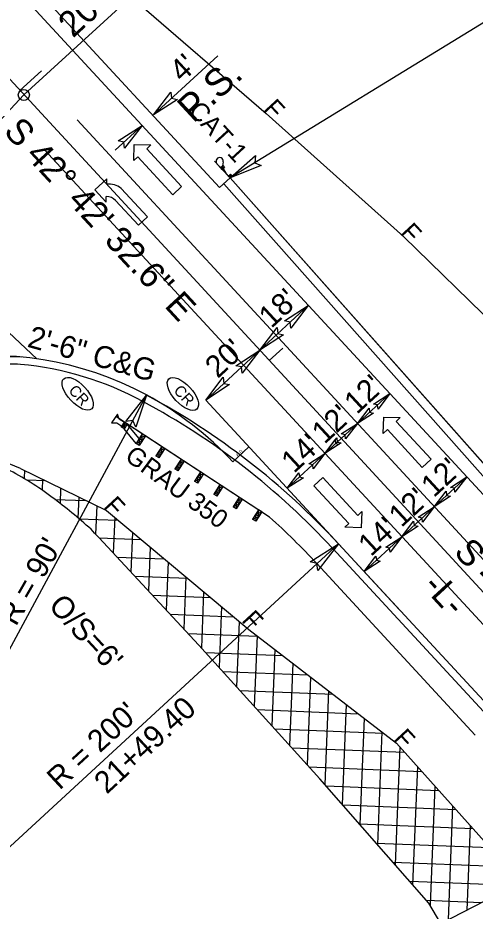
# Model space of a CAD drawing. Extents: x 1702862 to 1704514, y 793768 to 796215.
# Drawn here: x 1703331.8 to 1703456.2, y 795003.7 to 795246.9 of the extents above; entities that cross this region are included whole.
import ezdxf

# ---------------------------------------------------------------- set-up
doc = ezdxf.new("R2010")
doc.units = 0
for name, color, linetype in [('Default', 7, 'Continuous'), ('Prop Conc 2ft 6in Curb and Gutter', 7, 'Continuous'), ('Prop Conc Shoulder Berm Gutter', 7, 'Continuous'), ('Prop Dimension', 7, 'Continuous'), ('Prop Dimension Text', 7, 'Continuous'), ('Prop DSN Text', 7, 'Continuous'), ('Prop EOT', 7, 'Continuous'), ('Prop Guardrail', 7, 'Continuous'), ('Prop Guardrail Anchor Unit CELL', 7, 'Continuous'), ('Prop Horizontal Alignment', 7, 'Continuous'), ('Prop Horizontal Alignment Direction Label', 7, 'Continuous'), ('Prop Horizontal Alignment Station Label', 7, 'Continuous'), ('Prop Horizontal Alignment Tick Label', 7, 'Continuous'), ('Prop Horizontal Alignment Tick Large', 7, 'Continuous'), ('Prop Horizontal Alignment Tick Small', 7, 'Continuous'), ('Prop Lane Arrow CELL', 7, 'Continuous'), ('Prop Lane Lines', 7, 'Continuous'), ('Prop Leader Line Medium', 7, 'Continuous'), ('Prop Paved Shoulder', 7, 'Continuous'), ('Prop Rem of Exist Asph Pvmt', 7, 'Continuous'), ('Prop SS Fill Line', 7, 'Continuous'), ('Prop SS Misc', 7, 'Continuous'), ('Prop SS Transition Line', 7, 'Continuous'), ('Prop Structure Anchor Unit CELL', 7, 'Continuous'), ('Prop Superelevation  Arrow CELL', 7, 'Continuous'), ('Prop Terminator CELL', 7, 'Continuous'), ('Prop WCR CELL', 7, 'Continuous')]:
    doc.layers.add(name, color=color, linetype=linetype)

msp = doc.modelspace()

# ---------------------------------------------------------------- linework, layer by layer
at = {"layer": 'Default'}
msp.add_line((1703382.89, 795142.89), (1703435.5, 795085.89), dxfattribs=at)
at = {"layer": 'Prop Conc 2ft 6in Curb and Gutter'}
msp.add_line((1703417.51, 795102.43), (1703474.32, 795040.89), dxfattribs=at)
for centre, radius, start, end in [((1703330.77, 795134.69), 18, 84.5561, 126.0894), ((1703324.13, 795065.01), 88, 61.7203, 84.5561), ((1703272.02, 794968.13), 198, 42.7091, 61.7203)]:
    msp.add_arc(centre, radius, start, end, dxfattribs=at)
at = {"layer": 'Prop Conc Shoulder Berm Gutter'}
msp.add_line((1703389.53, 795203.37), (1703514.68, 795062.03), dxfattribs=at)
at = {"layer": 'Prop Dimension'}
for p, q in [((1703368.67, 795220.51), (1703386.16, 795236.65)), ((1703358.27, 795210.9), (1703365.58, 795217.66)), ((1703397.58, 795156.45), (1703410.81, 795168.66)), ((1703382.89, 795142.89), (1703397.58, 795156.45)), ((1703272.02, 794968.13), (1703366.77, 795144.26)), ((1703324.13, 795065.01), (1703366.77, 795144.26)), ((1703424.16, 795136.51), (1703432.98, 795144.65)), ((1703415.34, 795128.37), (1703424.16, 795136.51)), ((1703390.26, 795126.05), (1703394.67, 795130.12)), ((1703405.06, 795118.87), (1703415.34, 795128.37)), ((1703445.09, 795113.83), (1703453.91, 795121.97)), ((1703436.27, 795105.69), (1703445.09, 795113.83)), ((1703425.99, 795096.2), (1703436.27, 795105.69)), ((1703272.02, 794968.13), (1703418.98, 795103.79))]:
    msp.add_line(p, q, dxfattribs=at)
for start, end in [(136.7565, 136.7565), (42.7091, 61.7203)]:
    msp.add_arc((1703324.13, 795065.01), 90, start, end, dxfattribs=at)
at = {"layer": 'Prop EOT'}
for p, q in [((1703259.9, 795332.15), (1703737.14, 794815.13)), ((1703418.98, 795103.79), (1703631.9, 794873.13))]:
    msp.add_line(p, q, dxfattribs=at)
for centre, radius, start, end in [((1703324.13, 795065.01), 90, 61.7203, 136.7565), ((1703330.77, 795134.69), 20, 84.5561, 126.0894), ((1703272.02, 794968.13), 200, 42.7091, 61.7203)]:
    msp.add_arc(centre, radius, start, end, dxfattribs=at)
at = {"layer": 'Prop Guardrail'}
for p, q in [((1703389.53, 795203.37), (1703385.29, 795207.96)), ((1703518.92, 795057.44), (1703389.53, 795203.37)), ((1703400.26, 795111.03), (1703358.41, 795138.39)), ((1703413.1, 795098.36), (1703456.19, 795051.68))]:
    msp.add_line(p, q, dxfattribs=at)
msp.add_arc((1703272.02, 794968.13), 192, 42.7091, 48.0924, dxfattribs=at)
at = {"layer": 'Prop Guardrail Anchor Unit CELL'}
for p, q in [((1703387.12, 795205.97), (1703385.96, 795207.23)), ((1703386.94, 795206.17), (1703387.54, 795206.71)), ((1703387.42, 795205.65), (1703387.54, 795206.71)), ((1703387.66, 795207.73), (1703387.46, 795206.65)), ((1703387.54, 795206.71), (1703388.01, 795206.2)), ((1703386.94, 795206.17), (1703388.01, 795206.2)), ((1703387.42, 795205.65), (1703386.94, 795206.17)), ((1703387.03, 795206.07), (1703387.12, 795205.97)), ((1703389.53, 795203.37), (1703387.12, 795205.97)), ((1703388.01, 795206.2), (1703387.42, 795205.65)), ((1703387.48, 795206.18), (1703388.47, 795204.51)), ((1703389.05, 795203.88), (1703389.64, 795204.43)), ((1703389.53, 795203.37), (1703389.64, 795204.43)), ((1703389.64, 795204.43), (1703390.12, 795203.92)), ((1703389.05, 795203.88), (1703390.12, 795203.92)), ((1703389.53, 795203.37), (1703389.05, 795203.88)), ((1703390.12, 795203.92), (1703389.53, 795203.37)), ((1703358.88, 795139.09), (1703357.23, 795136.66)), ((1703359.37, 795137.72), (1703358.88, 795139.09)), ((1703357.23, 795136.66), (1703358.69, 795136.71)), ((1703358.69, 795136.71), (1703360.38, 795135.56)), ((1703361.07, 795136.57), (1703359.37, 795137.72)), ((1703360.71, 795136.89), (1703359.89, 795135.63)), ((1703359.89, 795135.63), (1703361.55, 795136.34)), ((1703360.38, 795135.56), (1703360.72, 795136.06)), ((1703360.71, 795136.89), (1703360.73, 795135.09)), ((1703360.72, 795136.06), (1703361.07, 795136.57)), ((1703361.55, 795136.34), (1703360.73, 795135.09)), ((1703400.26, 795111.03), (1703361.13, 795136.61)), ((1703364.81, 795132.38), (1703361.55, 795136.34)), ((1703360.73, 795135.09), (1703359.89, 795135.63)), ((1703360.73, 795135.09), (1703360.31, 795135.36)), ((1703363.98, 795131.09), (1703360.73, 795135.09)), ((1703365.65, 795133.66), (1703363.98, 795131.09)), ((1703365.65, 795131.83), (1703365.65, 795133.66)), ((1703363.98, 795131.09), (1703365.65, 795131.83)), ((1703366.49, 795133.11), (1703364.81, 795130.55)), ((1703366.49, 795133.11), (1703364.81, 795132.38)), ((1703365.65, 795131.83), (1703364.81, 795132.38)), ((1703364.81, 795132.38), (1703364.81, 795130.55)), ((1703364.81, 795130.55), (1703363.98, 795131.09)), ((1703370.93, 795130.21), (1703369.29, 795127.7)), ((1703371.76, 795129.66), (1703370.11, 795128.95)), ((1703370.94, 795128.41), (1703370.11, 795128.95)), ((1703370.11, 795128.95), (1703370.12, 795127.15)), ((1703371.76, 795129.66), (1703370.12, 795127.15)), ((1703370.94, 795128.41), (1703370.93, 795130.21)), ((1703369.29, 795127.7), (1703370.94, 795128.41)), ((1703370.12, 795127.15), (1703369.29, 795127.7)), ((1703376.2, 795126.76), (1703374.48, 795124.13)), ((1703376.18, 795124.9), (1703376.2, 795126.76)), ((1703374.48, 795124.13), (1703376.18, 795124.9)), ((1703375.32, 795123.59), (1703374.48, 795124.13)), ((1703377.04, 795126.21), (1703375.32, 795123.59)), ((1703375.34, 795125.45), (1703375.32, 795123.59)), ((1703377.04, 795126.21), (1703375.34, 795125.45)), ((1703376.18, 795124.9), (1703375.34, 795125.45)), ((1703381.47, 795123.31), (1703379.81, 795120.77)), ((1703379.81, 795120.77), (1703381.48, 795121.49)), ((1703382.31, 795122.76), (1703380.64, 795122.04)), ((1703381.48, 795121.49), (1703380.64, 795122.04)), ((1703380.64, 795122.04), (1703380.65, 795120.22)), ((1703382.31, 795122.76), (1703380.65, 795120.22)), ((1703382.31, 795122.76), (1703381.47, 795123.31)), ((1703381.48, 795121.49), (1703381.47, 795123.31)), ((1703380.65, 795120.22), (1703379.81, 795120.77)), ((1703386.75, 795119.86), (1703385.08, 795117.31)), ((1703387.58, 795119.31), (1703385.91, 795118.59)), ((1703387.58, 795119.31), (1703385.92, 795116.76)), ((1703386.75, 795118.04), (1703386.75, 795119.86)), ((1703385.08, 795117.31), (1703386.75, 795118.04)), ((1703385.92, 795116.76), (1703385.08, 795117.31)), ((1703386.75, 795118.04), (1703385.91, 795118.59)), ((1703385.91, 795118.59), (1703385.92, 795116.76)), ((1703392.02, 795116.41), (1703390.35, 795113.86)), ((1703390.35, 795113.86), (1703392.02, 795114.59)), ((1703392.86, 795115.87), (1703391.19, 795113.31)), ((1703392.86, 795115.87), (1703391.19, 795115.14)), ((1703392.02, 795114.59), (1703391.19, 795115.14)), ((1703391.19, 795115.14), (1703391.19, 795113.31)), ((1703392.02, 795114.59), (1703392.02, 795116.41)), ((1703391.19, 795113.31), (1703390.35, 795113.86)), ((1703397.29, 795112.96), (1703395.65, 795110.45)), ((1703397.29, 795112.96), (1703396.47, 795111.71)), ((1703396.47, 795111.71), (1703398.13, 795112.42)), ((1703398.13, 795112.42), (1703396.49, 795109.91)), ((1703398.13, 795112.42), (1703397.29, 795112.96)), ((1703397.31, 795111.16), (1703397.29, 795112.96)), ((1703395.65, 795110.45), (1703397.31, 795111.16)), ((1703396.49, 795109.91), (1703395.65, 795110.45)), ((1703397.31, 795111.16), (1703396.47, 795111.71)), ((1703396.47, 795111.71), (1703396.49, 795109.91))]:
    msp.add_line(p, q, dxfattribs=at)
msp.add_ellipse((1703386.69, 795207.91), major_axis=(-0.73, -0.674), ratio=0.995379, start_param=2.210226, end_param=6.283185, dxfattribs=at)
at = {"layer": 'Prop Horizontal Alignment'}
for p, q in [((1703246.67, 795319.94), (1703723.92, 794802.92)), ((1703333.42, 795225.96), (1703157.53, 795038.5))]:
    msp.add_line(p, q, dxfattribs=at)
at = {"layer": 'Prop Horizontal Alignment Station Label'}
msp.add_line((1703333.42, 795225.96), (1703408.81, 795294.97), dxfattribs=at)
msp.add_circle((1703333.42, 795225.96), 1.5, dxfattribs=at)
at = {"layer": 'Prop Horizontal Alignment Tick Large'}
msp.add_line((1703332.34, 795227.14), (1703338.22, 795232.56), dxfattribs=at)
at = {"layer": 'Prop Horizontal Alignment Tick Small'}
msp.add_line((1703400.17, 795153.65), (1703403.84, 795157.05), dxfattribs=at)
at = {"layer": 'Prop Lane Arrow CELL'}
for p, q in [((1703363.33, 795208.07), (1703363.47, 795212.49)), ((1703363.47, 795212.49), (1703367.96, 795212.34)), ((1703367.96, 795212.34), (1703366.86, 795211.32)), ((1703364.43, 795209.09), (1703363.33, 795208.07)), ((1703373.93, 795198.8), (1703364.43, 795209.09)), ((1703366.86, 795211.32), (1703376.35, 795201.04)), ((1703356.04, 795203.09), (1703352.77, 795200.14)), ((1703355.98, 795201.61), (1703356.04, 795203.09)), ((1703352.77, 795200.14), (1703355.79, 795196.8)), ((1703367.02, 795192.75), (1703359.86, 795200.5)), ((1703376.35, 795201.04), (1703373.93, 795198.8)), ((1703355.79, 795196.8), (1703355.85, 795198.29)), ((1703358.39, 795197.23), (1703364.59, 795190.51)), ((1703364.59, 795190.51), (1703367.02, 795192.75)), ((1703431.21, 795133.82), (1703431.35, 795138.24)), ((1703431.35, 795138.24), (1703435.84, 795138.1)), ((1703435.84, 795138.1), (1703434.74, 795137.08)), ((1703434.74, 795137.08), (1703444.24, 795126.79)), ((1703432.31, 795134.84), (1703431.21, 795133.82)), ((1703441.81, 795124.55), (1703432.31, 795134.84)), ((1703444.24, 795126.79), (1703441.81, 795124.55)), ((1703412.35, 795119.55), (1703414.77, 795121.78)), ((1703414.77, 795121.78), (1703424.27, 795111.5)), ((1703421.85, 795109.26), (1703412.35, 795119.55)), ((1703424.27, 795111.5), (1703425.37, 795112.51)), ((1703425.37, 795112.51), (1703425.23, 795108.1)), ((1703420.74, 795108.24), (1703421.85, 795109.26)), ((1703425.23, 795108.1), (1703420.74, 795108.24))]:
    msp.add_line(p, q, dxfattribs=at)
for centre, radius, start, end in [((1703356.6, 795196.41), 5.25, 51.3851, 96.6968), ((1703355.99, 795195.03), 3.27, 42.7091, 92.3672)]:
    msp.add_arc(centre, radius, start, end, dxfattribs=at)
at = {"layer": 'Prop Lane Lines'}
for p, q in [((1703347.89, 795219.14), (1703550.56, 794999.58)), ((1703339.07, 795211), (1703542.22, 794990.92))]:
    msp.add_line(p, q, dxfattribs=at)
at = {"layer": 'Prop Leader Line Medium'}
msp.add_line((1703493.18, 795266.98), (1703389.53, 795203.37), dxfattribs=at)
at = {"layer": 'Prop Paved Shoulder'}
for p, q in [((1703262.84, 795334.86), (1703386.66, 795200.72)), ((1703386.66, 795200.72), (1703389.53, 795203.37)), ((1703387.81, 795201.79), (1703512.55, 795060.91))]:
    msp.add_line(p, q, dxfattribs=at)
at = {"layer": 'Prop Rem of Exist Asph Pvmt'}
for p, q in [((1703333.62, 795123.68), (1703333.54, 795121.71)), ((1703334.48, 795121.15), (1703339.17, 795120.96)), ((1703338.53, 795121.28), (1703338.41, 795118.51)), ((1703343.43, 795118.88), (1703343.27, 795114.67)), ((1703341.81, 795115.85), (1703350.31, 795115.51)), ((1703348.34, 795116.47), (1703348.11, 795110.71)), ((1703353.25, 795114.07), (1703352.94, 795106.37)), ((1703348.26, 795110.59), (1703359.03, 795110.16)), ((1703358.13, 795110.91), (1703357.74, 795101.25)), ((1703352.67, 795106.65), (1703351.72, 795107.76)), ((1703352.67, 795106.65), (1703353.81, 795105.47)), ((1703353.91, 795105.36), (1703365.32, 795104.9)), ((1703362.97, 795106.87), (1703362.54, 795096.09)), ((1703367.81, 795102.82), (1703367.34, 795090.94)), ((1703358.75, 795100.16), (1703371.62, 795099.65)), ((1703372.65, 795098.78), (1703372.13, 795085.79)), ((1703363.59, 795094.96), (1703377.91, 795094.39)), ((1703377.5, 795094.74), (1703376.93, 795080.64)), ((1703382.34, 795090.69), (1703381.73, 795075.46)), ((1703368.43, 795089.77), (1703384.21, 795089.13)), ((1703387.18, 795086.65), (1703386.52, 795070.15)), ((1703373.27, 795084.57), (1703390.5, 795083.88)), ((1703392.02, 795082.61), (1703391.31, 795064.84)), ((1703378.11, 795079.37), (1703396.99, 795078.62)), ((1703396.87, 795078.71), (1703396.1, 795059.53)), ((1703382.89, 795074.18), (1703403.84, 795073.34)), ((1703401.72, 795074.97), (1703400.89, 795054.22)), ((1703406.58, 795071.23), (1703405.69, 795048.91)), ((1703387.57, 795068.98), (1703410.69, 795068.06)), ((1703411.43, 795067.48), (1703410.48, 795043.6)), ((1703392.26, 795063.79), (1703417.54, 795062.78)), ((1703416.29, 795063.74), (1703415.27, 795038.25)), ((1703396.94, 795058.6), (1703424.39, 795057.5)), ((1703421.14, 795060), (1703420.05, 795032.8)), ((1703426, 795056.26), (1703424.84, 795027.34)), ((1703401.63, 795053.41), (1703431.24, 795052.23)), ((1703430.85, 795052.52), (1703429.63, 795021.89)), ((1703406.31, 795048.22), (1703437.01, 795046.99)), ((1703435.69, 795048.47), (1703434.41, 795016.44)), ((1703410.99, 795043.03), (1703441.64, 795041.8)), ((1703440.48, 795043.1), (1703439.2, 795010.99)), ((1703415.63, 795037.84), (1703446.27, 795036.61)), ((1703445.27, 795037.73), (1703443.98, 795005.35)), ((1703420.18, 795032.65), (1703450.9, 795031.42)), ((1703450.06, 795032.37), (1703448.82, 795001.4)), ((1703424.73, 795027.47), (1703455.53, 795026.23)), ((1703454.85, 795027), (1703453.93, 795004.05)), ((1703429.29, 795022.28), (1703460.16, 795021.04)), ((1703433.84, 795017.09), (1703464.79, 795015.85)), ((1703446.88, 795000.39), (1703470.79, 795012.78)), ((1703446.88, 795000.39), (1703470.79, 795012.78)), ((1703438.39, 795011.91), (1703466.9, 795010.77)), ((1703442.94, 795006.72), (1703457.94, 795006.12))]:
    msp.add_line(p, q, dxfattribs=at)
msp.add_lwpolyline([(1703446.88, 795000.39), (1703443.63, 795005.93), (1703413.93, 795039.78), (1703381.07, 795076.19), (1703353.81, 795105.47)], dxfattribs=at)
msp.add_spline([(1703351.72, 795107.76), (1703341.14, 795116.4), (1703328.87, 795124.03), (1703320.09, 795127.66)], degree=3, dxfattribs=at)
at = {"layer": 'Prop SS Fill Line'}
for p, q in [((1703361.26, 795253.83), (1703399.32, 795220.91)), ((1703399.32, 795220.91), (1703436.73, 795187.4)), ((1703436.73, 795187.4), (1703472.51, 795152.39)), ((1703332.5, 795124.23), (1703355.89, 795112.78)), ((1703355.89, 795112.78), (1703394.59, 795080.46)), ((1703394.59, 795080.46), (1703434.77, 795049.5)), ((1703434.77, 795049.5), (1703468.06, 795012.19))]:
    msp.add_line(p, q, dxfattribs=at)
at = {"layer": 'Prop SS Transition Line'}
msp.add_arc((1703317.11, 795092.79), 35, 63.9216, 107.5505, dxfattribs=at)
at = {"layer": 'Prop Superelevation  Arrow CELL'}
msp.add_line((1703299.21, 795189.5), (1703336.95, 795154.09), dxfattribs=at)
at = {"layer": 'Prop Terminator CELL'}
for points in [[(1703375.18, 795224.73), (1703368.67, 795220.51), (1703373.4, 795226.72), (1703373.6, 795225.06)], [(1703359.07, 795213.44), (1703365.58, 795217.66), (1703360.85, 795211.44), (1703360.65, 795213.1)], [(1703398.01, 795206.76), (1703389.53, 795203.37), (1703396.4, 795209.47), (1703396.26, 795207.5)], [(1703404.3, 795164.44), (1703410.81, 795168.66), (1703406.08, 795162.45), (1703405.88, 795164.11)], [(1703404.1, 795160.67), (1703397.58, 795156.45), (1703402.31, 795162.67), (1703402.52, 795161.01)], [(1703391.07, 795152.23), (1703397.58, 795156.45), (1703392.85, 795150.24), (1703392.65, 795151.9)], [(1703389.4, 795147.11), (1703382.89, 795142.89), (1703387.62, 795149.1), (1703387.82, 795147.44)], [(1703361.14, 795137.07), (1703366.77, 795144.26), (1703363.89, 795135.54), (1703363.03, 795137.31)], [(1703428.57, 795141.79), (1703432.98, 795144.65), (1703429.78, 795140.44), (1703429.64, 795141.57)], [(1703428.57, 795139.36), (1703424.16, 795136.51), (1703427.36, 795140.71), (1703427.5, 795139.59)], [(1703419.75, 795133.65), (1703424.16, 795136.51), (1703420.96, 795132.3), (1703420.82, 795133.43)], [(1703419.75, 795131.22), (1703415.34, 795128.37), (1703418.54, 795132.57), (1703418.68, 795131.45)], [(1703419.18, 795130.85), (1703415.34, 795128.37), (1703418.13, 795132.03), (1703418.25, 795131.05)], [(1703410.94, 795125.51), (1703415.34, 795128.37), (1703412.14, 795124.16), (1703412.01, 795125.29)], [(1703409.46, 795121.73), (1703405.06, 795118.87), (1703408.26, 795123.08), (1703408.39, 795121.95)], [(1703449.5, 795119.12), (1703453.91, 795121.97), (1703450.71, 795117.77), (1703450.57, 795118.89)], [(1703449.5, 795116.69), (1703445.09, 795113.83), (1703448.29, 795118.04), (1703448.43, 795116.91)], [(1703440.68, 795110.98), (1703445.09, 795113.83), (1703441.89, 795109.63), (1703441.75, 795110.75)], [(1703440.68, 795108.55), (1703436.27, 795105.69), (1703439.47, 795109.9), (1703439.61, 795108.78)], [(1703431.87, 795102.84), (1703436.27, 795105.69), (1703433.07, 795101.49), (1703432.93, 795102.61)], [(1703411.31, 795098.82), (1703418.98, 795103.79), (1703413.41, 795096.48), (1703413.17, 795098.43)], [(1703430.39, 795099.05), (1703425.99, 795096.2), (1703429.19, 795100.4), (1703429.32, 795099.28)]]:
    msp.add_lwpolyline(points, close=True, dxfattribs=at)
at = {"layer": 'Prop WCR CELL'}
for centre in [(1703348.08, 795144.59), (1703376.68, 795144.57)]:
    msp.add_ellipse(centre, major_axis=(3.8, -4.12), ratio=0.462467, dxfattribs=at)

# ---------------------------------------------------------------- texts
at = {"layer": 'Prop Dimension'}
msp.add_text("O/S=6'", height=6, rotation=312.7091, dxfattribs=at).set_placement((1703339.86, 795086.65))
at = {"layer": 'Prop Dimension Text'}
for s, height, rotation, p in [("4'", 6, 42.7091, (1703376.49, 795229.18)), ("18'", 6, 42.7091, (1703400.76, 795162.23)), ('2\'-6" C&G', 6, 344.2431, (1703334.1, 795157.46)), ("20'", 6, 42.7091, (1703386.16, 795148.58)), ("12'", 6, 42.7091, (1703424, 795138.81)), ("12'", 6, 42.7091, (1703415.2, 795130.69)), ("14'", 6, 42.7091, (1703406.89, 795122.75)), ('6.0', 1, 42.7091, (1703391.7, 795127.37)), ("12'", 6, 42.7091, (1703444.93, 795116.14)), ("12'", 6, 42.7091, (1703436.13, 795108.02)), ("14'", 6, 42.7091, (1703427.82, 795100.08)), ("R = 90'", 6, 60.1006, (1703331.27, 795081.07)), ("R = 200'", 6, 42.7091, (1703343.13, 795036.53)), ('21+49.40', 6, 42.7091, (1703355.98, 795035.41))]:
    msp.add_text(s, height=height, rotation=rotation, dxfattribs=at).set_placement(p)
at = {"layer": 'Prop DSN Text'}
msp.add_text('P.S.', height=7.5, rotation=42.7091, dxfattribs=at).set_placement((1703379.53, 795218.07))
at = {"layer": 'Prop Guardrail Anchor Unit CELL'}
msp.add_text('CAT-1', height=5, rotation=312.7301, dxfattribs=at).set_placement((1703377.93, 795221.41))
at = {"layer": 'Prop Horizontal Alignment Direction Label'}
for s, p in [('S 42%%d 42\' 32.6" E', (1703327.66, 795215.83)), ('S 42%%d 42\' 32.6" E', (1703450.14, 795101.27)), ('-L-', (1703441.69, 795091.97))]:
    msp.add_text(s, height=7, rotation=312.7091, dxfattribs=at).set_placement(p)
at = {"layer": 'Prop Horizontal Alignment Tick Label'}
msp.add_text('20', height=7, rotation=42.7091, dxfattribs=at).set_placement((1703346.79, 795241.28))
at = {"layer": 'Prop SS Misc'}
for p in [(1703398.36, 795221.96), (1703435.57, 795188.26), (1703354.93, 795113.82), (1703392.47, 795082.8), (1703433.81, 795050.54)]:
    msp.add_text('F', height=5, rotation=312.7091, dxfattribs=at).set_placement(p)
at = {"layer": 'Prop Structure Anchor Unit CELL'}
msp.add_text('GRAU 350', height=5, rotation=323.4477, dxfattribs=at).set_placement((1703360.58, 795126.86))
at = {"layer": 'Prop WCR CELL'}
for p in [(1703345.39, 795145.32), (1703373.99, 795145.3)]:
    msp.add_text('CR', height=3, rotation=312.7091, dxfattribs=at).set_placement(p)

doc.saveas('drawing.dxf')
